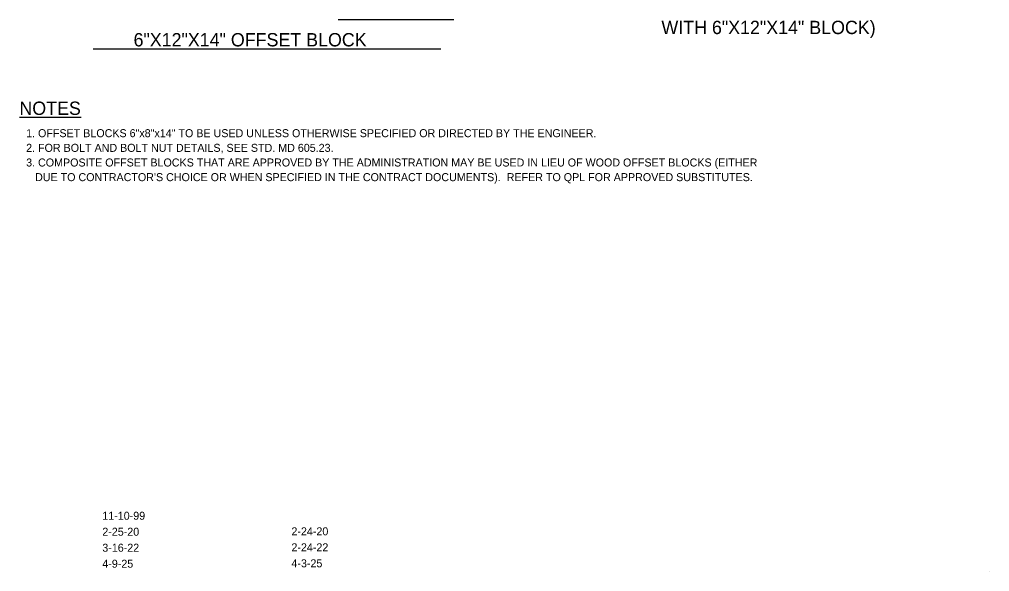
# Model space of a CAD drawing. Extents: x 12.3 to 19.6, y 6 to 16.3.
# Drawn here: x 12.35 to 19.62, y 5.98 to 10.13 of the extents above; entities that cross this region are included whole.
import ezdxf

# ---------------------------------------------------------------- set-up
doc = ezdxf.new("R2010")
doc.units = 0
for name, color, linetype in [('DETL-LINE', 7, 'Continuous'), ('DETL-NOTE', 7, 'Continuous'), ('DETL-TITL', 7, 'Continuous'), ('TTLB-TEXT', 7, 'Continuous')]:
    doc.layers.add(name, color=color, linetype=linetype)

msp = doc.modelspace()

# ---------------------------------------------------------------- linework, layer by layer
at = {"layer": 'DETL-LINE'}
msp.add_line((12.3454, 9.395), (12.8073, 9.395), dxfattribs=at)
at = {"layer": 'DETL-TITL'}
for p, q in [((14.7348, 10.1289), (15.6023, 10.1289)), ((12.8995, 9.9077), (15.505, 9.9077))]:
    msp.add_line(p, q, dxfattribs=at)
at = {"layer": 'TTLB-TEXT'}
msp.add_line((19.6208, 5.9844), (19.6208, 5.9844), dxfattribs=at)

# ---------------------------------------------------------------- texts
at = {"layer": 'DETL-NOTE'}
for s, height, p in [('NOTES', 0.1, (12.3454, 9.4121)), ('1. OFFSET BLOCKS 6"x8"x14" TO BE USED UNLESS OTHERWISE SPECIFIED OR DIRECTED BY THE ENGINEER.', 0.06, (12.396, 9.2449)), ('2. FOR BOLT AND BOLT NUT DETAILS, SEE STD. MD 605.23.', 0.06, (12.396, 9.1349)), ('3. COMPOSITE OFFSET BLOCKS THAT ARE APPROVED BY THE ADMINISTRATION MAY BE USED IN LIEU OF WOOD OFFSET BLOCKS (EITHER', 0.06, (12.396, 9.0249)), ("   DUE TO CONTRACTOR'S CHOICE OR WHEN SPECIFIED IN THE CONTRACT DOCUMENTS).  REFER TO QPL FOR APPROVED SUBSTITUTES.", 0.06, (12.396, 8.9149))]:
    msp.add_text(s, height=height, dxfattribs=at).set_placement(p)
at = {"layer": 'DETL-TITL'}
for s, p in [('WITH 6"X12"X14" BLOCK)', (17.1599, 10.0185)), ('6"X12"X14" OFFSET BLOCK', (13.2014, 9.9262))]:
    msp.add_text(s, height=0.1, dxfattribs=at).set_placement(p)
at = {"layer": 'TTLB-TEXT'}
for s, p in [('11-10-99', (12.9671, 6.3737)), ('2-25-20', (12.9671, 6.2537)), ('2-24-20', (14.3853, 6.2567)), ('3-16-22', (12.9671, 6.1337)), ('2-24-22', (14.3853, 6.1367))]:
    msp.add_text(s, height=0.06, rotation=360, dxfattribs=at).set_placement(p)
for s, p in [('4-9-25', (12.9671, 6.0137)), ('4-3-25', (14.3853, 6.0167))]:
    msp.add_text(s, height=0.06, dxfattribs=at).set_placement(p)

doc.saveas('drawing.dxf')
